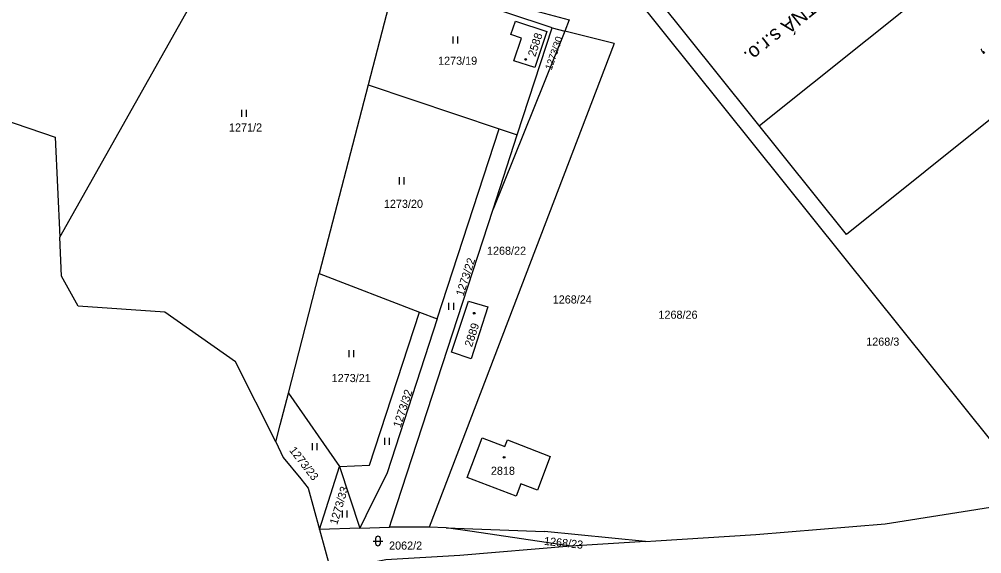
# Model space of a CAD drawing. Extents: x -793666 to -785424, y -1118958 to -1108761.
# Drawn here: x -792909 to -792706.7, y -1110162.1 to -1110049.8 of the extents above; entities that cross this region are included whole.
import ezdxf

# ---------------------------------------------------------------- set-up
doc = ezdxf.new("R2010")
doc.units = 0
for name, color, linetype in [('1_2000 - úřady', 7, 'Continuous'), ('Hranice parcel', 7, 'Continuous'), ('Parcelní čísla', 7, 'Continuous'), ('Vrstva 2', 7, 'Continuous'), ('Vrstva 62', 7, 'Continuous'), ('Značky budov', 7, 'Continuous'), ('Značky kultur', 7, 'Continuous')]:
    doc.layers.add(name, color=color, linetype=linetype)

msp = doc.modelspace()

# ---------------------------------------------------------------- linework, layer by layer
at = {"layer": '1_2000 - úřady'}
msp.add_lwpolyline([(-791938.08, -1109742.36), (-792598.01, -1110271.46), (-792786.15, -1110036.8), (-792126.22, -1109507.7)], close=True, dxfattribs=at)
at = {"layer": 'Hranice parcel'}
for p, q in [((-792900.49, -1110095.65), (-792863.09, -1110029.17)), ((-792829.75, -1110040.65), (-792835.69, -1110063.59)), ((-792797.02, -1110051.63), (-792829.75, -1110040.65)), ((-792802.91, -1110047.44), (-792793.42, -1110049.99)), ((-792793.42, -1110049.99), (-792794.36, -1110052.32)), ((-792794.36, -1110052.32), (-792809.43, -1110089.72)), ((-792804.37, -1110074.16), (-792797.02, -1110051.63)), ((-792797.02, -1110051.63), (-792794.36, -1110052.32)), ((-792783.99, -1110054.93), (-792794.36, -1110052.32)), ((-792783.99, -1110054.93), (-792822.84, -1110156.54)), ((-792835.69, -1110063.59), (-792845.96, -1110103.29)), ((-792835.69, -1110063.59), (-792808.16, -1110072.88)), ((-792821.18, -1110112.8), (-792808.16, -1110072.88)), ((-792808.16, -1110072.88), (-792804.37, -1110074.16)), ((-792809.43, -1110089.72), (-792804.37, -1110074.16)), ((-792852.45, -1110128.39), (-792845.96, -1110103.29)), ((-792845.96, -1110103.29), (-792824.89, -1110111.38)), ((-792824.89, -1110111.38), (-792821.18, -1110112.8)), ((-792852.45, -1110128.39), (-792841.73, -1110143.79)), ((-792845.9, -1110157.04), (-792841.73, -1110143.79)), ((-792841.73, -1110143.79), (-792837.45, -1110156.75)), ((-792837.45, -1110156.75), (-792831.19, -1110156.54)), ((-792822.84, -1110156.54), (-792831.19, -1110156.54)), ((-792819.27, -1110156.68), (-792822.84, -1110156.54)), ((-792837.45, -1110156.75), (-792845.9, -1110157.04)), ((-792845.9, -1110157.04), (-792843.51, -1110165.75)), ((-792819.27, -1110156.68), (-792798.67, -1110157.48)), ((-792777.43, -1110159.54), (-792798.67, -1110157.48)), ((-792777.43, -1110159.54), (-792793.11, -1110160.53)), ((-792777.43, -1110159.54), (-792775.23, -1110159.4))]:
    msp.add_line(p, q, dxfattribs=at)
for points in [[(-792804.73, -1110050.23), (-792798.16, -1110052.42), (-792800.69, -1110060.01), (-792805.06, -1110058.55), (-792803.5, -1110053.84), (-792805.68, -1110053.06), (-792804.73, -1110050.23)], [(-793004.01, -1110084.81), (-792986.75, -1110058.99), (-792967.73, -1110055.85), (-792929.82, -1110064.97), (-792901.45, -1110074.63), (-792900.49, -1110095.65)], [(-792831.19, -1110156.54), (-792830.69, -1110155.01), (-792809.43, -1110089.72)], [(-792855.09, -1110138.6), (-792863.56, -1110121.81), (-792878.42, -1110111.41), (-792896.64, -1110110.12), (-792900.12, -1110103.79), (-792900.49, -1110095.65)], [(-792810.56, -1110110.29), (-792814.04, -1110121.18), (-792818.19, -1110119.81), (-792814.6, -1110109.05), (-792810.56, -1110110.29)], [(-792841.73, -1110143.79), (-792835.38, -1110143.57), (-792824.89, -1110111.38)], [(-792821.18, -1110112.8), (-792831.72, -1110145.13), (-792836.19, -1110154.2), (-792837.45, -1110156.75)], [(-792855.09, -1110138.6), (-792854.18, -1110135.08), (-792852.45, -1110128.39)], [(-792814.91, -1110146.11), (-792811.76, -1110137.79), (-792806.95, -1110139.61), (-792806.42, -1110138.21), (-792797.43, -1110141.72), (-792800.14, -1110148.82), (-792803.63, -1110147.49), (-792804.6, -1110150.04), (-792814.91, -1110146.11)], [(-792855.09, -1110138.6), (-792853.58, -1110141.93), (-792849.84, -1110146.38), (-792848.29, -1110148.36), (-792845.9, -1110157.04)], [(-792775.23, -1110159.4), (-792754.22, -1110158.08), (-792727.01, -1110155.87), (-792700.93, -1110151.75)], [(-792793.11, -1110160.53), (-792813.86, -1110157.47), (-792819.27, -1110156.68)], [(-792793.11, -1110160.53), (-792816.41, -1110162.52), (-792831.95, -1110163.4), (-792843.51, -1110165.75)]]:
    msp.add_lwpolyline(points, dxfattribs=at)
at = {"layer": 'Vrstva 62'}
for p, q in [((-792625.32, -1109969.55), (-792753.42, -1110072.26)), ((-792607.04, -1109992.34), (-792735.15, -1110095.05)), ((-792735.15, -1110095.05), (-792778.45, -1110041.05))]:
    msp.add_line(p, q, dxfattribs=at)
at = {"layer": 'Značky budov'}
for centre in [(-792802.58, -1110058.29), (-792813.41, -1110111.6), (-792807.12, -1110141.89)]:
    msp.add_circle(centre, 0.175, dxfattribs=at)
at = {"layer": 'Značky kultur'}
for p, q in [((-792817.83, -1110054.95), (-792817.83, -1110053.45)), ((-792816.83, -1110054.95), (-792816.83, -1110053.45)), ((-792862.23, -1110070.38), (-792862.23, -1110068.88)), ((-792861.23, -1110070.38), (-792861.23, -1110068.88)), ((-792829.11, -1110084.53), (-792829.11, -1110083.03)), ((-792828.11, -1110084.53), (-792828.11, -1110083.03)), ((-792818.71, -1110110.93), (-792818.71, -1110109.43)), ((-792817.71, -1110110.93), (-792817.71, -1110109.43)), ((-792839.72, -1110120.87), (-792839.72, -1110119.37)), ((-792838.72, -1110120.87), (-792838.72, -1110119.37)), ((-792832.2, -1110139.27), (-792832.2, -1110137.77)), ((-792831.2, -1110139.27), (-792831.2, -1110137.77)), ((-792847.39, -1110140.38), (-792847.39, -1110138.88)), ((-792846.39, -1110140.38), (-792846.39, -1110138.88)), ((-792841.11, -1110154.55), (-792841.11, -1110153.05)), ((-792840.11, -1110154.55), (-792840.11, -1110153.05)), ((-792834.63, -1110159.47), (-792832.63, -1110159.47)), ((-792834.13, -1110158.97), (-792834.13, -1110159.97)), ((-792833.13, -1110159.97), (-792833.13, -1110158.97))]:
    msp.add_line(p, q, dxfattribs=at)
for centre, start, end in [((-792833.63, -1110158.97), 0, 180), ((-792833.63, -1110159.97), 180, 359.9879)]:
    msp.add_arc(centre, 0.5, start, end, dxfattribs=at)

# ---------------------------------------------------------------- texts
at = {"layer": 'Parcelní čísla'}
for s, height, rotation, p in [('2588', 1.7, 72, (-792800.58, -1110057.85)), ('1273/30', 1.502, 71, (-792797.15, -1110060.64)), ('1273/22', 1.7, 72, (-792815.7, -1110108.14)), ('2889', 1.7, 72, (-792813.89, -1110118.82)), ('1273/32', 1.7, 72, (-792828.89, -1110135.79)), ('1273/23', 1.7, 308, (-792852.37, -1110140.45)), ('1273/33', 1.7, 73, (-792842.22, -1110156.19)), ('1268/23', 1.7, 354, (-792798.8, -1110160.27))]:
    msp.add_text(s, height=height, rotation=rotation, dxfattribs=at).set_placement(p)
for s, p in [('1273/19', (-792821, -1110059.4)), ('1271/2', (-792864.94, -1110073.43)), ('1273/20', (-792832.39, -1110089.47)), ('1268/22', (-792810.73, -1110099.33)), ('1268/24', (-792796.91, -1110109.57)), ('1268/26', (-792774.69, -1110112.77)), ('1268/3', (-792731.03, -1110118.43)), ('1273/21', (-792843.37, -1110126.08)), ('2818', (-792809.9, -1110145.56)), ('2062/2', (-792831.3, -1110161.28))]:
    msp.add_text(s, height=1.7, dxfattribs=at).set_placement(p)
at = {"layer": 'Vrstva 2'}
msp.add_text('GEODÉZIE BLATNÁ s.r.o.', height=3.0008, rotation=218.721, dxfattribs=at).set_placement((-792719.98, -1110027.34))
at = {"layer": 'Vrstva 62'}
msp.add_text('Doplnění závor na přejezdech P1348 v km 23,017,', height=3.6, rotation=218.721, dxfattribs=at).set_placement((-792622.69, -1109989.39))

doc.saveas('drawing.dxf')
